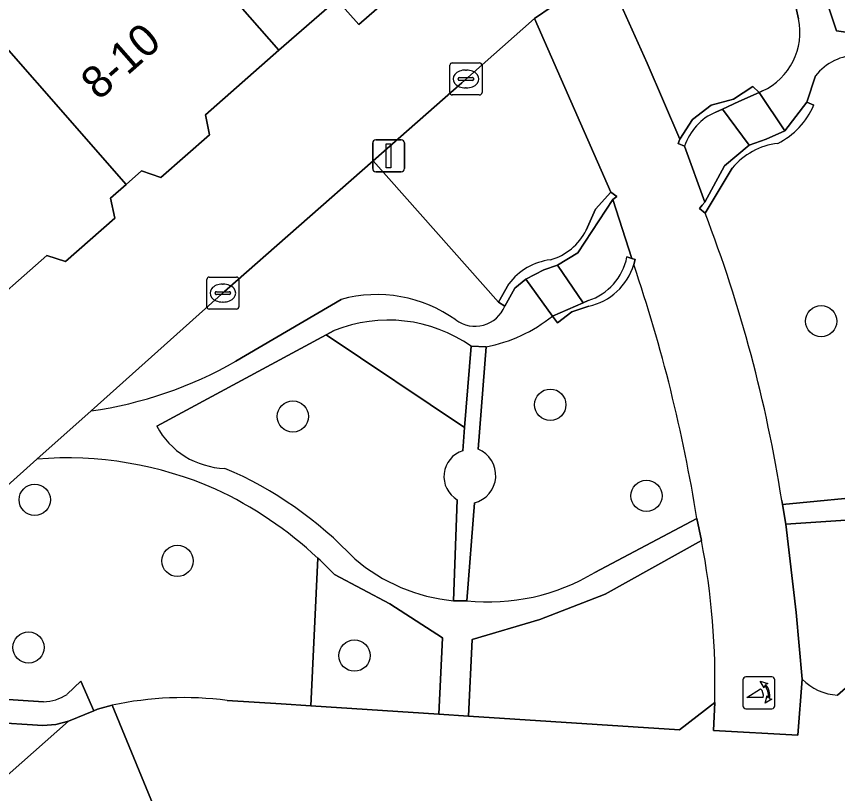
# Model space of a CAD drawing. Extents: x 159960 to 160866, y 382700 to 383354.
# Drawn here: x 160531.44 to 160557.07, y 383038.93 to 383063.19 of the extents above; entities that cross this region are included whole.
import ezdxf

# ---------------------------------------------------------------- set-up
doc = ezdxf.new("R2010")
doc.units = 0
for name, color, linetype in [('IMGEO_Boom', 7, 'Continuous'), ('IMGEO_Groenvoorziening', 7, 'Continuous'), ('IMGEO_Kolk', 7, 'Continuous'), ('IMGEO_Lichtmast', 7, 'Continuous'), ('IMGEO_Muur', 7, 'Continuous'), ('IMGEO_Pand', 7, 'Continuous'), ('IMGEO_Pand_nummerreeks', 7, 'Continuous'), ('IMGEO_Parkeervlak_open', 7, 'Continuous'), ('IMGEO_Poller', 7, 'Continuous'), ('IMGEO_Rijbaan_lokaal_open', 7, 'Continuous'), ('IMGEO_Terreindeel_open', 7, 'Continuous'), ('IMGEO_Voetpad_open', 7, 'Continuous')]:
    doc.layers.add(name, color=color, linetype=linetype)

msp = doc.modelspace()

# ---------------------------------------------------------------- linework, layer by layer
at = {"layer": 'IMGEO_Boom'}
for centre in [(160556.557, 383053.674), (160548.103, 383051.066), (160540.068, 383050.7), (160532.012, 383048.1), (160551.104, 383048.222), (160536.466, 383046.191), (160531.817, 383043.49), (160541.99, 383043.235)]:
    msp.add_circle(centre, 0.489, dxfattribs=at)
at = {"layer": 'IMGEO_Groenvoorziening'}
for points in [[(160555.845, 383063.114), (160554.869, 383067.547)], [(160553.272, 383067.214), (160551.918, 383066.516), (160551.165, 383065.258), (160550.589, 383064.77), (160549.905, 383064.449), (160551.123, 383061.734), (160552.145, 383059.353), (160552.544, 383059.972), (160553.128, 383060.42), (160553.823, 383060.604), (160554.422, 383061.002), (160554.62, 383060.818), (160554.722, 383060.865)], [(160556.072, 383066.732), (160556.793, 383063.458), (160557.037, 383062.743), (160558.623, 383062.509), (160561.238, 383061.772), (160565.872, 383059.127), (160566.858, 383060.379), (160567.218, 383061.45), (160567.562, 383062.471), (160567.668, 383063.425), (160567.768, 383064.329), (160566.765, 383064.176), (160564.725, 383064.134), (160562.93, 383064.723), (160562.684, 383064.804), (160564.48, 383061.63), (160564.291, 383061.545), (160563.144, 383063.401), (160562.18, 383065.358)], [(160549.22, 383056.516), (160549.514, 383057.168), (160549.987, 383057.706), (160547.614, 383063.12), (160545.337, 383061.117), (160542.574, 383058.683), (160546.484, 383054.264), (160546.805, 383054.841)], [(160556.377, 383061.337), (160556.105, 383060.515), (160556.325, 383060.424)], [(160546.684, 383054.14), (160546.484, 383054.264), (160542.574, 383058.683), (160537.937, 383054.599), (160533.771, 383050.874)], [(160553.78, 383058.456), (160552.934, 383057.049)], [(160538.29, 383052.426), (160541.572, 383054.355)], [(160549.301, 383054.14), (160548.77, 383053.967), (160548.326, 383053.627), (160548.174, 383053.834)], [(160545.368, 383049.63), (160545.426, 383050.352), (160541.107, 383053.247), (160535.818, 383050.401)], [(160541.357, 383053.382), (160541.107, 383053.247), (160545.426, 383050.352), (160545.629, 383052.892)], [(160546.096, 383052.874), (160545.849, 383049.68)], [(160532.081, 383049.37), (160528.98, 383046.59), (160529.25, 383046.25), (160528.189, 383045.31), (160527.865, 383045.02), (160530.689, 383041.896), (160532.284, 383041.79)], [(160545.078, 383044.949), (160545.199, 383048.102)], [(160555.327, 383048.08), (160555.35, 383047.948), (160558.375, 383048.24)], [(160557.069, 383042.001), (160558.146, 383042.949), (160561.724, 383046.104), (160563.22, 383044.446), (160565.039, 383046.025), (160566.534, 383044.321), (160568.349, 383045.885), (160569.807, 383044.202), (160571.772, 383045.911), (160571.074, 383047.346), (160568.932, 383048.275)], [(160545.733, 383048.004), (160545.501, 383044.949)], [(160549.49, 383045.831), (160552.676, 383047.515)], [(160558.422, 383047.541), (160555.456, 383047.334), (160555.775, 383044.585), (160555.962, 383042.499)], [(160552.82, 383046.831), (160549.82, 383045.156), (160547.774, 383044.357), (160545.669, 383043.733), (160545.55, 383041.347), (160552.137, 383040.918), (160553.234, 383041.773)], [(160538.021, 383041.837), (160539.707, 383041.727), (160540.63, 383041.667), (160540.85, 383046.274)], [(160540.85, 383046.274), (160540.63, 383041.667), (160544.622, 383041.407), (160544.736, 383043.789), (160543.096, 383044.856), (160541.363, 383045.766)], [(160533.024, 383042.026), (160533.445, 383042.435), (160533.857, 383041.513), (160533.968, 383041.559), (160534.432, 383041.689)]]:
    msp.add_lwpolyline(points, dxfattribs=at)
for centre, radius, start, end in [((160553.892, 383062.684), 2, 294.529, 12.4021), ((160557.7, 383060.29), 1.687, 89.7592, 141.6348), ((160554.171, 383061.317), 2.331, 296.2101, 337.4883), ((160555.455, 383057.057), 2.182, 96.6948, 140.1469), ((160511.917, 383041.302), 43.936, 8.875, 21.0029), ((160547.622, 383057.309), 1.784, 285.7392, 333.6084), ((160548.362, 383053.646), 1.963, 97.496, 142.4952), ((160548.886, 383055.998), 1.904, 282.6044, 342.9936), ((160505.31, 383039.95), 47.967, 9.0743, 18.8417), ((160542.689, 383050.278), 4.227, 54.3711, 105.3208), ((160545.75, 383054.528), 1.011, 233.637, 337.4228), ((160543.043, 383049.215), 4.495, 54.8822, 112.0313), ((160545.184, 383057.578), 4.791, 280.9758, 308.6165), ((160531.988, 383063.421), 12.673, 278.0886, 299.8203), ((160538.015, 383051.568), 2.488, 207.97, 268.4555), ((160545.625, 383048.828), 0.842, 107.7547, 239.6226), ((160545.516, 383048.861), 0.884, 284.2059, 67.8756), ((160533.003, 383037.808), 11.599, 66.3429, 94.5592), ((160533.197, 383037.963), 12.091, 43.2876, 66.8614), ((160532.406, 383037.221), 12.38, 46.9926, 64.9015), ((160530.085, 383042.424), 23.158, 358.3887, 10.9698), ((160532.467, 383037.295), 12.284, 43.5967, 46.9645), ((160545.623, 383050.525), 5.603, 229.6876, 264.4191), ((160546.183, 383051.327), 6.414, 263.8973, 301.0387), ((160557.155, 383043.672), 1.674, 224.517, 267.0404), ((160532.217, 383043.277), 1.489, 272.5678, 302.8092), ((160536.666, 383031.105), 10.817, 82.8042, 101.9185)]:
    msp.add_arc(centre, radius, start, end, dxfattribs=at)
at = {"layer": 'IMGEO_Kolk'}
for p, q in [((160544.97, 383060.811), (160544.97, 383061.663)), ((160545.045, 383061.737), (160545.897, 383061.737)), ((160545.971, 383061.663), (160545.971, 383060.811)), ((160545.458, 383061.517), (160545.483, 383061.517)), ((160545.229, 383061.231), (160545.229, 383061.243)), ((160545.667, 383061.194), (160545.269, 383061.194)), ((160545.272, 383061.28), (160545.67, 383061.28)), ((160545.713, 383061.243), (160545.713, 383061.231)), ((160545.481, 383060.957), (160545.456, 383060.957)), ((160545.897, 383060.737), (160545.045, 383060.737)), ((160537.457, 383055.053), (160538.309, 383055.053)), ((160537.382, 383054.127), (160537.382, 383054.979)), ((160537.87, 383054.833), (160537.895, 383054.833)), ((160538.383, 383054.979), (160538.383, 383054.127)), ((160537.641, 383054.547), (160537.641, 383054.559)), ((160538.079, 383054.51), (160537.681, 383054.51)), ((160537.684, 383054.596), (160538.082, 383054.596)), ((160538.125, 383054.559), (160538.125, 383054.547)), ((160537.893, 383054.273), (160537.868, 383054.273)), ((160538.309, 383054.053), (160537.457, 383054.053))]:
    msp.add_line(p, q, dxfattribs=at)
for points in [[(160544.97, 383060.811), (160544.97, 383061.663)], [(160545.045, 383061.737), (160545.897, 383061.737)], [(160545.971, 383061.663), (160545.971, 383060.811)], [(160545.897, 383060.737), (160545.045, 383060.737)], [(160537.457, 383055.053), (160538.309, 383055.053)], [(160537.382, 383054.127), (160537.382, 383054.979)], [(160538.383, 383054.979), (160538.383, 383054.127)], [(160538.309, 383054.053), (160537.457, 383054.053)]]:
    msp.add_lwpolyline(points, dxfattribs=at)
for centre, radius, start, end in [((160545.047, 383061.661), 0.0765, 91.552, 178.448), ((160545.047, 383061.661), 0.0765, 91.552, 178.448), ((160545.895, 383061.661), 0.0765, 1.552, 88.448), ((160545.895, 383061.661), 0.0765, 1.552, 88.448), ((160545.269, 383061.24), 0.0403, 85.8775, 175.7526), ((160545.266, 383061.23), 0.0366, 178.938, 274.7102), ((160545.67, 383061.237), 0.043, 264.8664, 352.4533), ((160545.674, 383061.242), 0.0386, 1.7309, 96.639), ((160545.047, 383060.813), 0.0765, 181.552, 268.448), ((160545.047, 383060.813), 0.0765, 181.552, 268.448), ((160545.895, 383060.813), 0.0765, 271.552, 358.448), ((160545.895, 383060.813), 0.0765, 271.552, 358.448), ((160537.459, 383054.977), 0.0765, 91.552, 178.448), ((160537.459, 383054.977), 0.0765, 91.552, 178.448), ((160538.307, 383054.977), 0.0765, 1.552, 88.448), ((160538.307, 383054.977), 0.0765, 1.552, 88.448), ((160537.681, 383054.556), 0.0403, 85.8775, 175.7526), ((160537.678, 383054.546), 0.0366, 178.938, 274.7102), ((160538.082, 383054.553), 0.043, 264.8664, 352.4533), ((160538.086, 383054.558), 0.0386, 1.7309, 96.639), ((160537.459, 383054.129), 0.0765, 181.552, 268.448), ((160537.459, 383054.129), 0.0765, 181.552, 268.448), ((160538.307, 383054.129), 0.0765, 271.552, 358.448), ((160538.307, 383054.129), 0.0765, 271.552, 358.448)]:
    msp.add_arc(centre, radius, start, end, dxfattribs=at)
for centre, major_axis, ratio, start_param, end_param in [((160545.457, 383061.237), (-0.387, 0.002), 0.722429, 4.712389, 7.853982), ((160545.482, 383061.237), (-0.39, 0.002), 0.717154, 1.570796, 4.712389), ((160537.869, 383054.553), (-0.387, 0.002), 0.722429, 4.712389, 7.853982), ((160537.894, 383054.553), (-0.39, 0.002), 0.717154, 1.570796, 4.712389)]:
    msp.add_ellipse(centre, major_axis=major_axis, ratio=ratio, start_param=start_param, end_param=end_param, dxfattribs=at)
at = {"layer": 'IMGEO_Lichtmast'}
for p, q in [((160542.659, 383059.339), (160543.449, 383059.339)), ((160543.449, 383059.339), (160542.659, 383059.339)), ((160542.559, 383058.439), (160542.559, 383059.239)), ((160542.559, 383059.239), (160542.559, 383058.439)), ((160543.549, 383059.239), (160543.549, 383058.439)), ((160543.549, 383058.439), (160543.549, 383059.239)), ((160543.449, 383058.339), (160542.659, 383058.339)), ((160542.659, 383058.339), (160543.449, 383058.339))]:
    msp.add_line(p, q, dxfattribs=at)
msp.add_lwpolyline([(160542.979, 383059.214), (160543.129, 383059.214), (160543.129, 383058.464), (160542.979, 383058.464), (160542.979, 383059.214)], dxfattribs=at)
for centre, start, end in [((160542.659, 383059.239), 90, 180), ((160542.659, 383059.239), 90, 180), ((160543.449, 383059.239), 0, 90), ((160543.449, 383059.239), 360, 90), ((160542.659, 383058.439), 180, 270), ((160542.659, 383058.439), 180, 270), ((160543.449, 383058.439), 270, 0), ((160543.449, 383058.439), 270, 0)]:
    msp.add_arc(centre, 0.1, start, end, dxfattribs=at)
at = {"layer": 'IMGEO_Muur'}
for points in [[(160553.268, 383060.201), (160553.478, 383060.297), (160553.987, 383060.529), (160554.62, 383060.818), (160554.422, 383061.002), (160553.823, 383060.604), (160553.128, 383060.42), (160552.544, 383059.972), (160552.145, 383059.353), (160552.094, 383059.22), (160552.295, 383059.135)], [(160556.325, 383060.424), (160556.105, 383060.515), (160555.418, 383059.615), (160554.844, 383059.357), (160554.307, 383059.171), (160553.541, 383058.527), (160552.921, 383057.396), (160552.842, 383057.296), (160552.761, 383057.198), (160552.934, 383057.049), (160553.78, 383058.456)], [(160546.805, 383054.841), (160546.484, 383054.264), (160546.684, 383054.14), (160546.998, 383054.706), (160547.34, 383054.982), (160547.901, 383055.274), (160548.324, 383055.426), (160548.967, 383055.805), (160550.056, 383057.469), (160550.175, 383057.572), (160549.987, 383057.706), (160549.514, 383057.168), (160549.22, 383056.516)], [(160550.706, 383055.441), (160550.747, 383055.598), (160550.644, 383055.631), (160550.494, 383055.68)], [(160549.289, 383054.318), (160549.131, 383054.25), (160548.647, 383054.039), (160548.174, 383053.834), (160548.326, 383053.627), (160548.77, 383053.967), (160549.301, 383054.14)]]:
    msp.add_lwpolyline(points, dxfattribs=at)
for centre, radius, start, end in [((160554.171, 383061.317), 2.331, 296.2101, 337.4883), ((160553.944, 383058.607), 1.732, 112.9869, 162.2361), ((160555.455, 383057.057), 2.182, 96.6948, 140.1469), ((160547.622, 383057.309), 1.784, 285.7392, 333.6084), ((160548.362, 383053.646), 1.963, 97.496, 142.4952), ((160548.73, 383056.027), 1.798, 288.1222, 348.8776), ((160548.886, 383055.998), 1.904, 282.6044, 342.9936)]:
    msp.add_arc(centre, radius, start, end, dxfattribs=at)
at = {"layer": 'IMGEO_Pand'}
for points in [[(160539.632, 383062.132), (160541.437, 383063.72), (160542.131, 383062.942), (160545.173, 383065.602), (160541.882, 383069.367), (160538.794, 383072.9), (160538.53, 383072.667), (160536.182, 383070.6), (160535.266, 383071.641), (160535.473, 383071.823), (160532.722, 383074.949), (160530.268, 383072.789)], [(160539.632, 383062.132), (160530.268, 383072.789), (160527.915, 383070.718), (160531.632, 383066.495), (160529.228, 383064.379), (160534.867, 383057.942), (160535.348, 383058.365), (160535.948, 383058.162), (160537.465, 383059.497), (160537.34, 383060.115)], [(160520.95, 383064.512), (160530.16, 383053.768), (160532.388, 383055.729), (160532.968, 383055.534), (160534.507, 383056.888), (160534.381, 383057.514), (160534.867, 383057.942), (160529.228, 383064.379), (160526.791, 383062.234), (160525.713, 383063.459), (160525.951, 383063.668), (160523.35, 383066.624)]]:
    msp.add_lwpolyline(points, close=True, dxfattribs=at)
at = {"layer": 'IMGEO_Parkeervlak_open'}
msp.add_lwpolyline([(160513.301, 383023.684), (160533.07, 383041.19), (160532.669, 383041.084), (160532.263, 383041.05), (160530.617, 383041.161)], dxfattribs=at)
at = {"layer": 'IMGEO_Poller'}
for p, q in [((160554.115, 383042.476), (160554.115, 383041.669)), ((160554.115, 383042.476), (160554.115, 383041.669)), ((160555.017, 383042.571), (160554.209, 383042.571)), ((160555.017, 383042.571), (160554.209, 383042.571)), ((160555.111, 383041.669), (160555.111, 383042.476)), ((160555.111, 383041.669), (160555.111, 383042.476)), ((160554.209, 383041.574), (160555.017, 383041.574)), ((160554.209, 383041.574), (160555.017, 383041.574))]:
    msp.add_line(p, q, dxfattribs=at)
for points in [[(160554.794, 383042.3), (160554.782, 383042.227), (160554.657, 383042.432)], [(160554.657, 383042.432), (160554.888, 383042.366), (160554.817, 383042.334)], [(160554.75, 383041.927), (160554.237, 383041.927), (160554.667, 383042.202)], [(160554.81, 383041.755), (160554.876, 383041.986), (160554.906, 383041.918)], [(160554.942, 383041.891), (160555.014, 383041.88), (160554.81, 383041.755)]]:
    msp.add_lwpolyline(points, dxfattribs=at)
for centre, radius, start, end in [((160554.209, 383042.476), 0.0946, 90, 180), ((160554.209, 383042.476), 0.0946, 90, 180), ((160555.017, 383042.476), 0.0946, 0, 90), ((160555.017, 383042.476), 0.0946, 0, 90), ((160554.422, 383041.977), 0.332, 351.3247, 42.4854), ((160554.436, 383041.987), 0.476, 351.7527, 41.1691), ((160554.436, 383041.987), 0.516, 349.3569, 42.2912), ((160554.209, 383041.669), 0.0946, 180, 270), ((160554.209, 383041.669), 0.0946, 180, 270), ((160555.017, 383041.669), 0.0946, 270, 0), ((160555.017, 383041.669), 0.0946, 270, 0)]:
    msp.add_arc(centre, radius, start, end, dxfattribs=at)
at = {"layer": 'IMGEO_Rijbaan_lokaal_open'}
for points in [[(160552.934, 383057.049), (160552.761, 383057.198), (160552.842, 383057.296), (160552.921, 383057.396), (160552.295, 383059.135), (160552.094, 383059.22), (160552.145, 383059.353), (160551.123, 383061.734), (160549.905, 383064.449), (160549.819, 383064.636), (160547.614, 383063.12), (160549.987, 383057.706), (160550.175, 383057.572), (160550.056, 383057.469), (160550.644, 383055.631), (160550.747, 383055.598), (160550.706, 383055.441)], [(160553.234, 383041.773), (160553.192, 383040.892), (160555.833, 383040.752), (160555.962, 383042.499), (160555.775, 383044.585), (160555.456, 383047.334), (160555.35, 383047.948), (160555.327, 383048.08)], [(160552.676, 383047.515), (160552.82, 383046.831)], [(160567.082, 383041.833), (160566.22, 383041.059), (160564.704, 383042.729), (160562.908, 383041.181), (160561.407, 383042.847), (160559.615, 383041.295), (160558.146, 383042.949), (160557.069, 383042.001)], [(160555.962, 383042.499), (160555.833, 383040.752), (160553.192, 383040.892), (160553.234, 383041.773), (160552.137, 383040.918), (160545.55, 383041.347), (160544.622, 383041.407), (160540.63, 383041.667), (160539.707, 383041.727), (160538.021, 383041.837)], [(160535.945, 383037.991), (160534.432, 383041.689), (160533.968, 383041.559), (160533.857, 383041.513), (160533.07, 383041.19), (160513.301, 383023.684), (160514.675, 383022.129), (160515.772, 383020.855), (160533.374, 383036.497)], [(160534.432, 383041.689), (160535.945, 383037.991), (160536.727, 383038.232), (160539.927, 383038.211), (160544.399, 383037.938), (160545.839, 383037.815), (160550.314, 383037.553), (160552.342, 383037.405), (160556.782, 383037.126), (160558.267, 383037.012), (160562.712, 383036.737), (160564.703, 383036.55), (160569.161, 383036.263), (160570.698, 383036.172), (160575.238, 383035.92), (160577.251, 383035.747), (160581.707, 383035.46), (160585.928, 383030.861), (160590.181, 383030.558), (160590.095, 383029.585)]]:
    msp.add_lwpolyline(points, dxfattribs=at)
for centre, radius, start, end in [((160511.917, 383041.302), 43.936, 8.875, 21.0029), ((160505.31, 383039.95), 47.967, 9.0743, 18.8417), ((160530.085, 383042.424), 23.158, 358.3887, 10.9698), ((160557.155, 383043.672), 1.674, 224.517, 267.0404), ((160536.666, 383031.105), 10.817, 82.8042, 101.9185)]:
    msp.add_arc(centre, radius, start, end, dxfattribs=at)
at = {"layer": 'IMGEO_Terreindeel_open'}
for points in [[(160554.62, 383060.818), (160553.987, 383060.529), (160553.478, 383060.297), (160554.307, 383059.171), (160554.844, 383059.357), (160555.418, 383059.615)], [(160548.324, 383055.426), (160547.901, 383055.274), (160547.34, 383054.982), (160548.174, 383053.834), (160548.647, 383054.039), (160549.131, 383054.25)]]:
    msp.add_lwpolyline(points, close=True, dxfattribs=at)
at = {"layer": 'IMGEO_Voetpad_open'}
for points in [[(160554.869, 383067.547), (160555.845, 383063.114)], [(160568.843, 383056.337), (160569.639, 383058.911), (160566.858, 383060.379), (160565.872, 383059.127), (160561.238, 383061.772), (160558.623, 383062.509), (160557.037, 383062.743), (160556.793, 383063.458), (160556.072, 383066.732)], [(160545.173, 383065.602), (160542.131, 383062.942), (160541.437, 383063.72), (160539.632, 383062.132), (160537.34, 383060.115), (160537.465, 383059.497), (160535.948, 383058.162), (160535.348, 383058.365), (160534.867, 383057.942), (160534.381, 383057.514), (160534.507, 383056.888), (160532.968, 383055.534), (160532.388, 383055.729), (160530.16, 383053.768)], [(160532.081, 383049.37), (160533.771, 383050.874), (160537.937, 383054.599), (160542.574, 383058.683), (160545.337, 383061.117), (160547.614, 383063.12), (160549.819, 383064.636)], [(160554.722, 383060.865), (160554.62, 383060.818), (160555.418, 383059.615), (160556.105, 383060.515), (160556.377, 383061.337)], [(160552.295, 383059.135), (160552.921, 383057.396), (160553.541, 383058.527), (160554.307, 383059.171), (160553.478, 383060.297), (160553.268, 383060.201)], [(160550.056, 383057.469), (160548.967, 383055.805), (160548.324, 383055.426)], [(160550.644, 383055.631), (160550.056, 383057.469)], [(160550.494, 383055.68), (160550.644, 383055.631)], [(160548.324, 383055.426), (160549.131, 383054.25)], [(160548.174, 383053.834), (160547.34, 383054.982), (160546.998, 383054.706), (160546.684, 383054.14)], [(160541.572, 383054.355), (160538.29, 383052.426)], [(160549.131, 383054.25), (160549.289, 383054.318)], [(160535.818, 383050.401), (160541.107, 383053.247), (160541.357, 383053.382)], [(160545.849, 383049.68), (160546.096, 383052.874), (160545.629, 383052.892), (160545.426, 383050.352), (160545.368, 383049.63)], [(160545.629, 383052.892), (160546.096, 383052.874)], [(160533.771, 383050.874), (160532.081, 383049.37)], [(160505.58, 383027.472), (160506.93, 383028.69), (160515.275, 383036.456), (160514.81, 383036.989), (160518.545, 383040.319), (160522.812, 383035.601), (160523.725, 383036.41), (160521.272, 383039.124), (160524.254, 383041.791), (160527.865, 383045.02), (160528.189, 383045.31), (160529.25, 383046.25), (160528.98, 383046.59), (160532.081, 383049.37)], [(160545.199, 383048.102), (160545.078, 383044.949), (160545.501, 383044.949), (160545.733, 383048.004)], [(160558.375, 383048.24), (160555.35, 383047.948), (160555.456, 383047.334), (160558.422, 383047.541)], [(160541.363, 383045.766), (160543.096, 383044.856), (160544.736, 383043.789), (160544.622, 383041.407), (160545.55, 383041.347), (160545.669, 383043.733), (160547.774, 383044.357), (160549.82, 383045.156), (160552.82, 383046.831), (160552.676, 383047.515), (160549.49, 383045.831)], [(160545.501, 383044.949), (160545.078, 383044.949)], [(160530.617, 383041.161), (160532.263, 383041.05), (160532.669, 383041.084), (160533.07, 383041.19), (160533.857, 383041.513), (160533.445, 383042.435), (160533.024, 383042.026)], [(160532.284, 383041.79), (160530.689, 383041.896), (160530.301, 383041.922)]]:
    msp.add_lwpolyline(points, dxfattribs=at)
for centre, radius, start, end in [((160553.892, 383062.684), 2, 294.529, 12.4021), ((160557.7, 383060.29), 1.687, 89.7592, 141.6348), ((160553.944, 383058.607), 1.732, 112.9869, 162.2361), ((160548.73, 383056.027), 1.798, 288.1222, 348.8776), ((160542.689, 383050.278), 4.227, 54.3711, 105.3208), ((160545.75, 383054.528), 1.011, 233.637, 337.4228), ((160543.043, 383049.215), 4.495, 54.8822, 112.0313), ((160545.184, 383057.578), 4.791, 280.9758, 308.6165), ((160531.988, 383063.421), 12.673, 278.0886, 299.8203), ((160538.015, 383051.568), 2.488, 207.97, 268.4555), ((160545.625, 383048.828), 0.842, 107.7547, 239.6226), ((160545.516, 383048.861), 0.884, 284.2059, 67.8756), ((160533.003, 383037.808), 11.599, 66.3429, 94.5592), ((160533.197, 383037.963), 12.091, 43.2876, 66.8614), ((160532.406, 383037.221), 12.38, 46.9926, 64.9015), ((160532.467, 383037.295), 12.284, 43.5967, 46.9645), ((160545.623, 383050.525), 5.603, 229.6876, 264.4191), ((160546.183, 383051.327), 6.414, 263.8973, 301.0387), ((160532.217, 383043.277), 1.489, 272.5678, 302.8092)]:
    msp.add_arc(centre, radius, start, end, dxfattribs=at)

# ---------------------------------------------------------------- texts
at = {"layer": 'IMGEO_Pand_nummerreeks'}
msp.add_text('8-10', height=1, rotation=41.3265, dxfattribs=at).set_placement((160534.009, 383060.543))

doc.saveas('drawing.dxf')
